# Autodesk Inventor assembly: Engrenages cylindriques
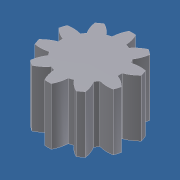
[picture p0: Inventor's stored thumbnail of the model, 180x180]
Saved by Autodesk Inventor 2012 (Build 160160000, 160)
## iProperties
Created: 2011-10
Part Number: Engrenages cylindriques
Document SubType Name: Assembly
Designer: Laur
ClientObjectVersion: 1
Author: Laur
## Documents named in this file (2)
- D:\Formulaire\Sujet CIM 2012\Modélisation_7970_shimano\Mobile intermédiaire 37 dents m0,25 - 10 dents m0,3\Design Accelerator\Engrenages cylindriques2.iam
- D:\Formulaire\Sujet CIM 2012\Modélisation_7970_shimano\Mobile intermédiaire 37 dents m0,25 - 10 dents m0,3\Design Accelerator\Engrenage cylindrique11.ipt
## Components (1 placed, 1 different names)
1. Engrenage cylindrique1:1
